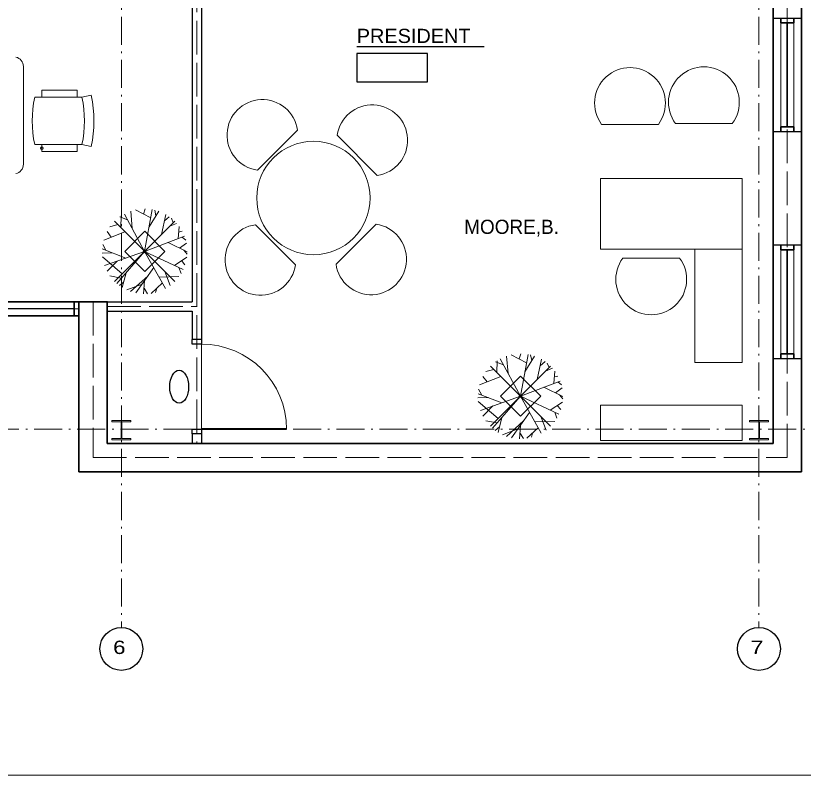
# Model space of a CAD drawing. Extents: x -118748 to -117136, y -118748 to -117596.
# Drawn here: x -117726.1 to -117459.3, y -118748.4 to -118491.2 of the extents above; entities that cross this region are included whole.
import ezdxf
from ezdxf.enums import TextEntityAlignment as Align

# ---------------------------------------------------------------- set-up
doc = ezdxf.new("R2010")
doc.units = 0
doc.header["$LTSCALE"] = 1.9
doc.header["$PDMODE"] = 32
doc.header["$PDSIZE"] = 0.95
for name, pattern in [('DOT_DASHED', [7.7, 5, -1.2, 0.3, -1.2]), ('LONG_DASHED', [7.5, 6, -1.5]), ('MEDIUM_DASHED', [4.5, 3, -1.5])]:
    doc.linetypes.add(name, pattern=pattern)
for name, color, linetype, lineweight in [('10', 7, 'DOT_DASHED', 13), ('11', 7, 'Continuous', 25), ('12', 7, 'Continuous', 13), ('15', 7, 'Continuous', 13), ('16', 7, 'Continuous', 13), ('17', 7, 'Continuous', 25), ('2', 7, 'Continuous', 35), ('23', 7, 'Continuous', 25), ('25', 7, 'Continuous', 13), ('26', 7, 'Continuous', 25), ('3', 7, 'Continuous', 35), ('30', 7, 'Continuous', 13), ('4', 7, 'Continuous', 35), ('42', 7, 'Continuous', 25), ('45', 7, 'Continuous', 25), ('5', 7, 'Continuous', 13), ('6', 7, 'Continuous', 13), ('60', 7, 'LONG_DASHED', 13), ('8', 7, 'MEDIUM_DASHED', 13), ('9', 7, 'Continuous', 35)]:
    doc.layers.add(name, color=color, linetype=linetype, lineweight=lineweight)
doc.layers.add('53', color=7, linetype='Continuous')

msp = doc.modelspace()

# ---------------------------------------------------------------- linework, layer by layer
at = {"layer": '10'}
for p, q in [((-117690.321, -117628.339), (-117690.321, -118698.41)), ((-117474.321, -117628.339), (-117474.321, -118698.41)), ((-118641.571, -118631.21), (-117285.521, -118631.21))]:
    msp.add_line(p, q, dxfattribs=at)
at = {"layer": '11'}
for centre in [(-117690.321, -118705.61), (-117474.321, -118705.61)]:
    msp.add_circle(centre, 7.253, dxfattribs=at)
at = {"layer": '12'}
for points in [[(-117693.504, -118634.762), (-117687.088, -118634.762), (-117687.088, -118634.366), (-117690.172, -118634.366), (-117690.172, -118628.662), (-117687.088, -118628.662), (-117687.088, -118628.266), (-117693.504, -118628.266), (-117693.504, -118628.662), (-117690.42, -118628.662), (-117690.42, -118634.366), (-117693.504, -118634.366)], [(-117477.504, -118634.762), (-117471.088, -118634.762), (-117471.088, -118634.366), (-117474.172, -118634.366), (-117474.172, -118628.662), (-117471.088, -118628.662), (-117471.088, -118628.266), (-117477.504, -118628.266), (-117477.504, -118628.662), (-117474.42, -118628.662), (-117474.42, -118634.366), (-117477.504, -118634.366)]]:
    msp.add_lwpolyline(points, close=True, dxfattribs=at)
at = {"layer": '15', "lineweight": 25}
for p, q in [((-117469.521, -118492.01), (-117469.521, -118343.21)), ((-117459.921, -118492.01), (-117459.921, -118352.81)), ((-117469.521, -118492.01), (-117459.921, -118492.01)), ((-117469.521, -118530.41), (-117459.921, -118530.41)), ((-117469.521, -118568.81), (-117469.521, -118530.41)), ((-117459.921, -118568.81), (-117459.921, -118530.41)), ((-117469.521, -118568.81), (-117459.921, -118568.81)), ((-117695.121, -118588.01), (-117704.721, -118588.01)), ((-117704.721, -118588.01), (-117704.721, -118645.61)), ((-117695.121, -118588.01), (-117695.121, -118636.01)), ((-117469.521, -118607.21), (-117459.921, -118607.21)), ((-117469.521, -118636.01), (-117469.521, -118607.21)), ((-117459.921, -118645.61), (-117459.921, -118607.21)), ((-117695.121, -118636.01), (-117469.521, -118636.01)), ((-117704.721, -118645.61), (-117459.921, -118645.61))]:
    msp.add_line(p, q, dxfattribs=at)
at = {"layer": '15'}
for p, q in [((-117723.492, -118541.486), (-117723.492, -118508.352)), ((-117717.267, -118516.402), (-117705.267, -118516.402)), ((-117717.267, -118516.402), (-117717.267, -118518.802)), ((-117705.267, -118518.802), (-117705.267, -118516.402)), ((-117703.667, -118518.802), (-117700.539, -118518.126)), ((-117719.667, -118518.802), (-117703.667, -118518.802)), ((-117717.267, -118518.802), (-117705.267, -118518.802)), ((-117508.41, -118527.961), (-117527.61, -118527.961)), ((-117483.379, -118527.68), (-117502.579, -118527.68)), ((-117630.643, -118529.885), (-117644.22, -118543.462)), ((-117603.644, -118545.25), (-117617.22, -118531.673)), ((-117719.667, -118534.802), (-117703.667, -118534.802)), ((-117717.267, -118534.802), (-117705.267, -118534.802)), ((-117717.267, -118534.802), (-117717.267, -118537.202)), ((-117717.267, -118537.202), (-117705.267, -118537.202)), ((-117705.267, -118537.202), (-117705.267, -118534.802)), ((-117703.667, -118534.802), (-117700.539, -118535.478)), ((-117644.883, -118561.947), (-117631.306, -118575.524)), ((-117617.602, -118575.343), (-117604.026, -118561.767)), ((-117520.42, -118573.242), (-117501.22, -118573.242))]:
    msp.add_line(p, q, dxfattribs=at)
for points in [[(-117528.056, -118546.242), (-117480.056, -118546.242), (-117480.056, -118570.242), (-117528.056, -118570.242)], [(-117496.056, -118570.242), (-117480.056, -118570.242), (-117480.056, -118608.642), (-117496.056, -118608.642)], [(-117480.056, -118623.042), (-117480.056, -118635.042), (-117528.056, -118635.042), (-117528.056, -118623.042)]]:
    msp.add_lwpolyline(points, close=True, dxfattribs=at)
msp.add_circle((-117625.248, -118552.895), 19.2, dxfattribs=at)
for centre, radius, start, end in [((-117726.692, -118508.351), 3.2, 0, 79.20527), ((-117518.01, -118520.761), 12, 323.1301, 216.8699), ((-117492.979, -118520.48), 12, 323.1301, 216.8699), ((-117740.675, -118526.802), 41.063, 347.80217, 12.19783), ((-117682.659, -118526.802), 37.863, 167.80217, 192.19783), ((-117740.675, -118526.802), 37.863, 347.80217, 12.19783), ((-117740.675, -118526.802), 37.863, 347.80217, 12.19783), ((-117642.522, -118531.582), 12, 8.1301, 261.8699), ((-117605.341, -118533.371), 12, 278.1301, 171.86989), ((-117726.692, -118541.486), 3.2, 280.79473, 0), ((-117643.186, -118573.826), 12, 98.1301, 351.8699), ((-117605.723, -118573.646), 12, 188.1301, 81.86989), ((-117510.82, -118580.442), 12, 143.1301, 36.86989)]:
    msp.add_arc(centre, radius, start, end, dxfattribs=at)
msp.add_point((-117717.267, -118536.002), dxfattribs=at)
at = {"layer": '16'}
for p, q in [((-117469.521, -118530.41), (-117469.521, -118492.01)), ((-117466.903, -118528.81), (-117466.903, -118493.61)), ((-117462.539, -118493.61), (-117462.539, -118528.81)), ((-117459.921, -118492.01), (-117459.921, -118530.41)), ((-117469.521, -118607.21), (-117469.521, -118568.81)), ((-117459.921, -118568.81), (-117459.921, -118607.21)), ((-117466.903, -118605.61), (-117466.903, -118570.41)), ((-117462.539, -118570.41), (-117462.539, -118605.61))]:
    msp.add_line(p, q, dxfattribs=at)
at = {"layer": '16', "lineweight": 35}
for p, q in [((-117464.721, -118528.81), (-117464.721, -118493.61)), ((-117464.721, -118605.61), (-117464.721, -118570.41))]:
    msp.add_line(p, q, dxfattribs=at)
for points in [[(-117466.903, -118492.01), (-117466.903, -118493.61), (-117462.539, -118493.61), (-117462.539, -118492.01)], [(-117466.903, -118530.41), (-117466.903, -118528.81), (-117462.539, -118528.81), (-117462.539, -118530.41)], [(-117466.903, -118568.81), (-117466.903, -118570.41), (-117462.539, -118570.41), (-117462.539, -118568.81)], [(-117466.903, -118607.21), (-117466.903, -118605.61), (-117462.539, -118605.61), (-117462.539, -118607.21)]]:
    msp.add_lwpolyline(points, dxfattribs=at)
at = {"layer": '17'}
msp.add_line((-117610.582, -118501.603), (-117567.382, -118501.603), dxfattribs=at)
at = {"layer": '2', "lineweight": 13}
msp.add_lwpolyline([(-118748.365, -118748.365), (-117365.965, -118748.365), (-117365.965, -117826.765), (-118748.365, -117826.765), (-118748.365, -118748.365), (-117135.565, -118748.365), (-117135.565, -117596.365), (-118748.365, -117596.365)], close=True, dxfattribs=at)
at = {"layer": '23'}
for p, q in [((-117666.321, -118456.81), (-117666.321, -118588.01)), ((-117663.121, -118456.81), (-117663.121, -118600.81)), ((-117695.121, -118588.01), (-117695.121, -118591.21)), ((-117695.121, -118588.01), (-117666.321, -118588.01)), ((-117695.121, -118591.21), (-117666.321, -118591.21)), ((-117666.321, -118591.21), (-117666.321, -118600.81)), ((-117663.121, -118600.81), (-117666.321, -118600.81)), ((-117663.121, -118632.81), (-117666.321, -118632.81)), ((-117666.321, -118632.81), (-117666.321, -118636.01)), ((-117663.121, -118632.81), (-117663.121, -118636.01)), ((-117663.121, -118636.01), (-117666.321, -118636.01))]:
    msp.add_line(p, q, dxfattribs=at)
at = {"layer": '25', "lineweight": 40}
msp.add_line((-117634.321, -118631.21), (-117663.121, -118631.21), dxfattribs=at)
at = {"layer": '25'}
msp.add_arc((-117663.121, -118631.21), 28.8, 359.99998, 89.99998, dxfattribs=at)
at = {"layer": '26'}
for points in [[(-117663.121, -118600.81), (-117663.121, -118602.41), (-117666.321, -118602.41), (-117666.321, -118600.81)], [(-117666.321, -118632.81), (-117666.321, -118631.21), (-117663.121, -118631.21), (-117663.121, -118632.81)]]:
    msp.add_lwpolyline(points, dxfattribs=at)
at = {"layer": '3'}
msp.add_lwpolyline([(-118098.321, -117954.41), (-117829.521, -117954.41), (-117459.921, -117954.41), (-117459.921, -118170.41), (-117370.321, -118170.41), (-117370.321, -118352.81), (-117459.921, -118352.81), (-117459.921, -118645.61), (-117704.721, -118645.61), (-117704.721, -118592.81), (-117847.121, -118592.81), (-117850.321, -118592.801), (-117860.744, -118590.984), (-117862.249, -118590.443), (-117871.571, -118585.668), (-117872.847, -118584.703), (-117880.323, -118577.368), (-117881.254, -118576.067), (-117886.205, -118566.837), (-117886.706, -118565.318), (-117888.682, -118555.032), (-117888.707, -118553.433), (-117890.316, -118553.433)], dxfattribs=at)
at = {"layer": '30'}
for p, q in [((-117682.422, -118570.973), (-117689.297, -118558.32)), ((-117686.62, -118563.248), (-117687.16, -118557.375)), ((-117680.347, -118559.649), (-117685.549, -118556.917)), ((-117682.839, -118558.34), (-117682.247, -118556.575)), ((-117682.422, -118570.973), (-117679.827, -118556.809)), ((-117680.903, -118562.682), (-117677.669, -118557.381)), ((-117678.608, -118558.921), (-117679.019, -118556.981)), ((-117676.717, -118565.269), (-117675.281, -118558.469)), ((-117672.24, -118560.791), (-117692.605, -118581.156)), ((-117672.24, -118581.156), (-117692.605, -118560.791)), ((-117688.205, -118560.33), (-117690.888, -118559.324)), ((-117690.485, -118562.91), (-117690.339, -118558.945)), ((-117675.742, -118560.653), (-117674.077, -118559.239)), ((-117672.711, -118561.262), (-117673.368, -118559.776)), ((-117691.5, -118561.896), (-117694.182, -118562.662)), ((-117673.928, -118562.479), (-117671.6, -118561.475)), ((-117671.1, -118566.671), (-117670.756, -118562.532)), ((-117689.091, -118564.305), (-117696.303, -118567.141)), ((-117693.759, -118566.14), (-117695.167, -118564.271)), ((-117682.422, -118570.973), (-117668.961, -118565.859)), ((-117670.916, -118564.459), (-117669.732, -118564.167)), ((-117669.758, -118566.162), (-117668.532, -118567.176)), ((-117695.556, -118570.597), (-117696.624, -118568.594)), ((-117674.492, -118567.96), (-117668.023, -118571.075)), ((-117670.573, -118569.847), (-117668.298, -118568.169)), ((-117693.375, -118571.438), (-117696.812, -118571.528)), ((-117688.746, -118573.222), (-117696.797, -118570.119)), ((-117682.422, -118570.973), (-117695.99, -118575.798)), ((-117682.422, -118570.973), (-117691.898, -118581.817)), ((-117682.422, -118570.973), (-117675.377, -118583.532)), ((-117682.422, -118570.973), (-117669.39, -118577.099)), ((-117669.197, -118570.51), (-117668.053, -118571.911)), ((-117690.004, -118578.555), (-117696.704, -118572.816)), ((-117691.749, -118574.29), (-117695.155, -118577.699)), ((-117672.37, -118575.699), (-117668.159, -118572.952)), ((-117669.939, -118574.114), (-117668.761, -118575.527)), ((-117679.334, -118576.48), (-117685.409, -118585.06)), ((-117670.811, -118576.431), (-117670.092, -118578.412)), ((-117690.345, -118580.04), (-117694.195, -118579.266)), ((-117688.744, -118578.208), (-117690.013, -118583.211)), ((-117681.365, -118579.349), (-117687.174, -118584.567)), ((-117677.523, -118579.707), (-117670.838, -118579.527)), ((-117675.577, -118577.819), (-117673.754, -118582.472)), ((-117689.552, -118581.393), (-117690.967, -118582.564)), ((-117683.273, -118582.044), (-117688.472, -118584.041)), ((-117682.435, -118580.86), (-117682.761, -118585.37)), ((-117676.422, -118581.67), (-117680.214, -118585.203)), ((-117682.619, -118583.407), (-117681.431, -118585.339)), ((-117678.322, -118583.441), (-117678.723, -118584.89)), ((-117559.311, -118612.285), (-117559.851, -118606.413)), ((-117553.039, -118608.686), (-117558.24, -118605.954)), ((-117555.531, -118607.377), (-117554.938, -118605.612)), ((-117555.114, -118620.011), (-117552.518, -118605.847)), ((-117553.594, -118611.72), (-117550.36, -118606.418)), ((-117551.3, -118607.958), (-117551.71, -118606.019)), ((-117560.897, -118609.367), (-117563.579, -118608.362)), ((-117563.177, -118611.948), (-117563.03, -118607.982)), ((-117555.114, -118620.011), (-117561.988, -118607.358)), ((-117549.409, -118614.306), (-117547.972, -118607.507)), ((-117548.434, -118609.691), (-117546.768, -118608.276)), ((-117545.403, -118610.3), (-117546.059, -118608.814)), ((-117564.191, -118610.934), (-117566.873, -118611.7)), ((-117544.931, -118609.829), (-117565.296, -118630.193)), ((-117544.931, -118630.193), (-117565.296, -118609.829)), ((-117546.62, -118611.517), (-117544.291, -118610.512)), ((-117543.791, -118615.709), (-117543.447, -118611.57)), ((-117561.782, -118613.342), (-117568.994, -118616.178)), ((-117566.45, -118615.178), (-117567.859, -118613.308)), ((-117543.607, -118613.496), (-117542.424, -118613.205)), ((-117555.114, -118620.011), (-117541.653, -118614.896)), ((-117547.183, -118616.998), (-117540.714, -118620.112)), ((-117543.265, -118618.884), (-117540.99, -118617.206)), ((-117542.45, -118615.199), (-117541.223, -118616.213)), ((-117561.437, -118622.259), (-117569.488, -118619.156)), ((-117568.248, -118619.634), (-117569.316, -118617.631)), ((-117555.114, -118620.011), (-117568.682, -118624.835)), ((-117555.114, -118620.011), (-117564.589, -118630.854)), ((-117555.114, -118620.011), (-117548.069, -118632.57)), ((-117555.114, -118620.011), (-117542.082, -118626.136)), ((-117541.888, -118619.547), (-117540.744, -118620.949)), ((-117566.066, -118620.475), (-117569.503, -118620.565)), ((-117562.695, -118627.592), (-117569.395, -118621.854)), ((-117545.061, -118624.736), (-117540.85, -118621.99)), ((-117564.441, -118623.327), (-117567.846, -118626.737)), ((-117542.631, -118623.151), (-117541.453, -118624.565)), ((-117561.436, -118627.246), (-117562.704, -118632.248)), ((-117552.025, -118625.517), (-117558.1, -118634.098)), ((-117548.268, -118626.857), (-117546.446, -118631.51)), ((-117543.502, -118625.468), (-117542.784, -118627.449)), ((-117563.037, -118629.078), (-117566.887, -118628.303)), ((-117562.243, -118630.43), (-117563.658, -118631.602)), ((-117554.056, -118628.386), (-117559.865, -118633.604)), ((-117555.126, -118629.898), (-117555.452, -118634.407)), ((-117550.215, -118628.744), (-117543.529, -118628.564)), ((-117555.965, -118631.081), (-117561.163, -118633.079)), ((-117555.31, -118632.444), (-117554.122, -118634.377)), ((-117549.113, -118630.708), (-117552.905, -118634.24)), ((-117551.013, -118632.478), (-117551.414, -118633.928))]:
    msp.add_line(p, q, dxfattribs=at)
for points in [[(-117675.57, -118570.97), (-117682.358, -118577.758), (-117689.146, -118570.97), (-117682.358, -118564.182)], [(-117548.261, -118620.008), (-117555.049, -118626.796), (-117561.837, -118620.008), (-117555.049, -118613.219)]]:
    msp.add_lwpolyline(points, close=True, dxfattribs=at)
for p in [(-117682.422, -118570.973), (-117555.114, -118620.011)]:
    msp.add_point(p, dxfattribs=at)
at = {"layer": '4'}
msp.add_lwpolyline([(-118496.721, -117964.01), (-118496.721, -118636.01), (-118271.121, -118636.01), (-118271.121, -118588.01), (-118115.969, -118588.01), (-118106.1, -118586.234), (-118096.66, -118581.314), (-118089.115, -118573.804), (-118084.156, -118564.399), (-118081.154, -118548.633), (-118079.134, -118548.633), (-117884.057, -118548.587), (-117881.646, -118565.336), (-117876.897, -118574.111), (-117869.271, -118581.538), (-117859.789, -118586.351), (-117850.271, -118588.01), (-117695.121, -118588.01), (-117695.121, -118636.01), (-117469.521, -118636.01), (-117469.521, -117964.01)], close=True, dxfattribs=at)
at = {"layer": '42'}
msp.add_ellipse((-117670.721, -118616.81), major_axis=(0, -5.6), ratio=0.571429, dxfattribs=at)
at = {"layer": '45'}
msp.add_lwpolyline([(-117610.582, -118504.003), (-117610.582, -118513.603), (-117586.582, -118513.603), (-117586.582, -118504.003)], close=True, dxfattribs=at)
at = {"layer": '5'}
for points in [[(-117979.078, -117964.01), (-117469.521, -117964.01), (-117469.521, -118636.01), (-117695.121, -118636.01), (-117695.121, -118588.01), (-117850.271, -118588.01)], [(-117840.35, -118423.21), (-117666.321, -118423.21), (-117666.321, -118456.81), (-117666.321, -118588.01), (-117706.321, -118588.01), (-117847.121, -118588.01), (-117850.321, -118588.001), (-117859.12, -118586.467), (-117860.626, -118585.926), (-117868.676, -118581.84), (-117869.952, -118580.875), (-117876.419, -118574.577), (-117877.349, -118573.275), (-117881.646, -118565.336), (-117882.147, -118563.816), (-117883.883, -118554.958), (-117883.908, -118477.769)]]:
    msp.add_lwpolyline(points, dxfattribs=at)
msp.add_lwpolyline([(-117663.121, -118636.01), (-117663.121, -118632.81), (-117663.121, -118423.21), (-117469.521, -118423.21), (-117469.521, -118636.01)], close=True, dxfattribs=at)
at = {"layer": '6'}
msp.add_lwpolyline([(-117850.321, -118588.001), (-117695.121, -118588.01), (-117695.121, -118636.01), (-117469.521, -118636.01), (-117469.521, -118423.21), (-117840.35, -118423.21)], dxfattribs=at)
at = {"layer": '60'}
for p, q in [((-117664.721, -118421.61), (-117664.721, -118636.01)), ((-117699.921, -118588.01), (-117699.921, -118640.81)), ((-117695.121, -118589.61), (-117664.721, -118589.61)), ((-117699.921, -118640.81), (-117464.721, -118640.81))]:
    msp.add_line(p, q, dxfattribs=at)
msp.add_lwpolyline([(-117464.721, -118640.81), (-117464.721, -118348.01), (-117375.121, -118348.01)], dxfattribs=at)
at = {"layer": '8'}
msp.add_line((-117704.721, -118590.41), (-117848.721, -118590.41), dxfattribs=at)
at = {"layer": '9', "lineweight": 13}
for p, q in [((-117706.321, -118588.01), (-117847.121, -118588.01)), ((-117706.321, -118592.81), (-117847.121, -118592.81))]:
    msp.add_line(p, q, dxfattribs=at)
at = {"layer": '9', "lineweight": 25}
msp.add_line((-117706.321, -118590.41), (-117733.201, -118590.41), dxfattribs=at)
at = {"layer": '9'}
msp.add_lwpolyline([(-117706.321, -118592.81), (-117704.721, -118592.81), (-117704.721, -118588.01), (-117706.321, -118588.01)], close=True, dxfattribs=at)

# ---------------------------------------------------------------- texts
at = {"layer": '11'}
for s, width, p in [(' 6 ', 1.25, (-117691.018, -118707.31)), (' 7 ', 1.3, (-117475.001, -118707.31))]:
    msp.add_text(s, height=4.518, dxfattribs=dict(at, width=width)).set_placement(p, align=Align.CENTER)
at = {"layer": '17', "width": 1.05}
msp.add_text('PRESIDENT', height=4.8, dxfattribs=at).set_placement((-117610.582, -118500.403))
at = {"layer": '53'}
msp.add_text('MOORE,B.', height=4.8, dxfattribs=at).set_placement((-117574.179, -118565.052))

doc.saveas('drawing.dxf')
